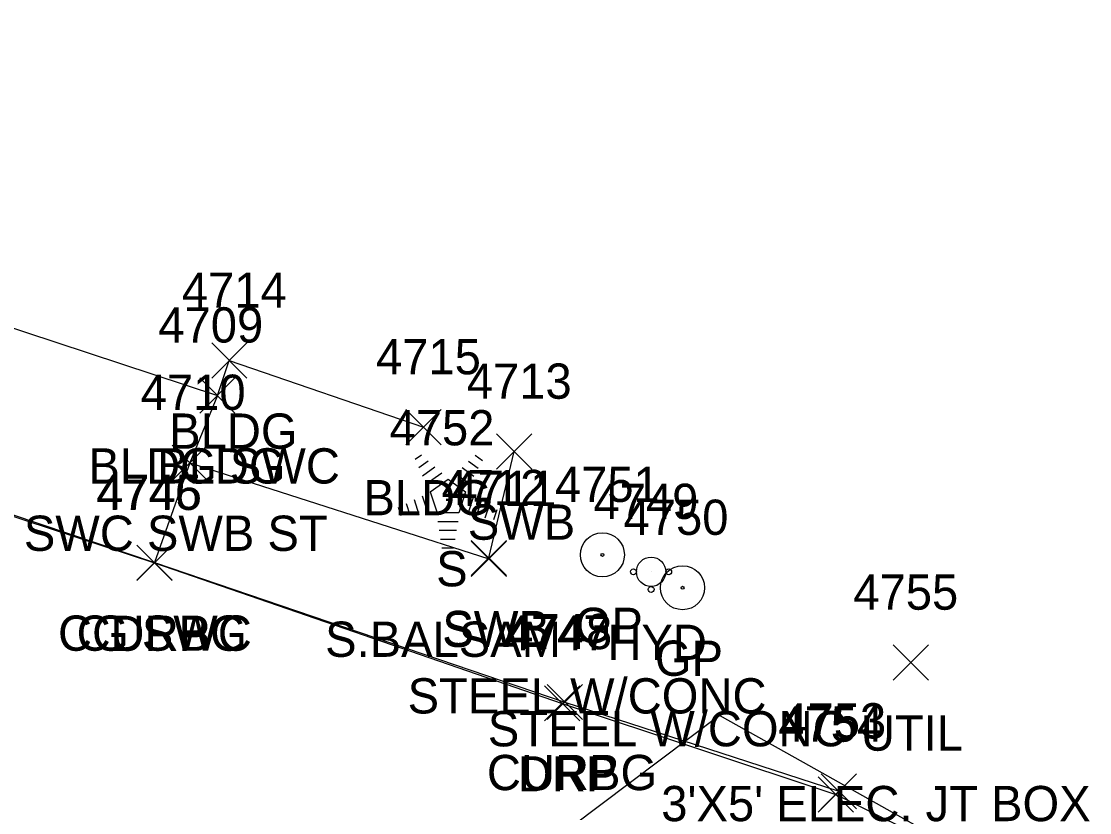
# Model space of a CAD drawing. Extents: x 49137 to 50946, y 9590 to 10709.
# Drawn here: x 50314.2 to 50374.8, y 10186.5 to 10231.4 of the extents above; entities that cross this region are included whole.
import ezdxf

# ---------------------------------------------------------------- set-up
doc = ezdxf.new("R2010")
doc.units = 0
for name, color, linetype in [('L_A', 7, 'Continuous'), ('L_C', 7, 'Continuous'), ('L_I', 7, 'Continuous'), ('L_TIC', 7, 'Continuous'), ('LBC', 7, 'Continuous'), ('LSOGP', 7, 'Continuous'), ('LTC', 7, 'Continuous'), ('PET', 7, 'Continuous'), ('R_A', 7, 'Continuous'), ('R_C', 7, 'Continuous'), ('R_I', 7, 'Continuous'), ('R_TIC', 7, 'Continuous'), ('RC', 7, 'Continuous'), ('RDP', 7, 'Continuous'), ('RGP', 7, 'Continuous'), ('RSW', 7, 'Continuous'), ('U_A', 7, 'Continuous'), ('U_C', 7, 'Continuous'), ('U_I', 7, 'Continuous'), ('UDEFAULT', 7, 'Continuous'), ('UWFH', 7, 'Continuous')]:
    doc.layers.add(name, color=color, linetype=linetype)

msp = doc.modelspace()

# ---------------------------------------------------------------- linework, layer by layer
at = {"layer": 'L_TIC'}
for points in [[(50325.045, 10211.173), (50327.045, 10213.173)], [(50327.045, 10211.173), (50325.045, 10213.173)], [(50324.367, 10209.198), (50326.367, 10211.198)], [(50326.367, 10209.198), (50324.367, 10211.198)], [(50336.06, 10207.397), (50338.06, 10209.397)], [(50338.06, 10207.397), (50336.06, 10209.397)]]:
    msp.add_lwpolyline(points, dxfattribs=at)
at = {"layer": 'LBC'}
msp.add_lwpolyline([(50282.222, 10227.148), (50292.804, 10223.645), (50292.299, 10221.382), (50307.138, 10216.211), (50325.367, 10210.198), (50326.045, 10212.173), (50337.06, 10208.397)], dxfattribs=at)
at = {"layer": 'LSOGP'}
msp.add_lwpolyline([(50368.109, 10184.028), (50363.359, 10186.695), (50358.609, 10189.361), (50353.858, 10192.028), (50331.98, 10175.564)], dxfattribs=at)
at = {"layer": 'LTC'}
for p, q in [((50336.59, 10206.572), (50336.944, 10206.83)), ((50339.988, 10206.813), (50340.407, 10206.508)), ((50336.799, 10206.107), (50337.329, 10206.491)), ((50339.617, 10206.464), (50340.166, 10206.065)), ((50337.009, 10205.641), (50337.713, 10206.152)), ((50337.219, 10205.175), (50338.097, 10205.813)), ((50338.875, 10205.768), (50339.684, 10205.179)), ((50339.246, 10206.116), (50339.925, 10205.622)), ((50337.443, 10204.72), (50338.455, 10205.455)), ((50338.455, 10205.455), (50339.452, 10204.73)), ((50336.989, 10204.501), (50337.319, 10203.482)), ((50337.443, 10204.72), (50337.83, 10203.527)), ((50339.452, 10204.73), (50339.061, 10203.527)), ((50339.889, 10204.459), (50339.551, 10203.419)), ((50335.622, 10203.851), (50335.774, 10203.383)), ((50336.078, 10204.068), (50336.289, 10203.416)), ((50336.533, 10204.285), (50336.804, 10203.449)), ((50340.334, 10204.208), (50340.046, 10203.324)), ((50340.779, 10203.958), (50340.541, 10203.229)), ((50339.061, 10203.527), (50337.83, 10203.527)), ((50341.223, 10203.708), (50341.036, 10203.134)), ((50339.022, 10203.027), (50337.878, 10203.027)), ((50338.939, 10202.527), (50337.95, 10202.527)), ((50338.855, 10202.027), (50338.023, 10202.027)), ((50338.771, 10201.527), (50338.096, 10201.527))]:
    msp.add_line(p, q, dxfattribs=at)
at = {"layer": 'PET'}
msp.add_lwpolyline([(50372.857, 10181.363), (50360.448, 10187.548)], dxfattribs=at)
at = {"layer": 'R_TIC'}
for points in [[(50324.367, 10209.198), (50326.367, 10211.198)], [(50326.367, 10209.198), (50324.367, 10211.198)], [(50341.21, 10206.009), (50343.21, 10208.009)], [(50343.21, 10206.009), (50341.21, 10208.009)], [(50322.8, 10205.377), (50324.8, 10207.377)], [(50324.8, 10205.377), (50322.8, 10207.377)], [(50322.8, 10205.377), (50324.8, 10207.377)], [(50324.8, 10205.377), (50322.8, 10207.377)], [(50339.772, 10199.922), (50341.772, 10201.922)], [(50341.772, 10199.922), (50339.772, 10201.922)], [(50339.773, 10199.974), (50341.773, 10201.974)], [(50341.773, 10199.974), (50339.773, 10201.974)], [(50320.801, 10199.709), (50322.801, 10201.709)], [(50322.801, 10199.709), (50320.801, 10201.709)], [(50320.801, 10199.709), (50322.801, 10201.709)], [(50322.801, 10199.709), (50320.801, 10201.709)], [(50320.808, 10199.695), (50322.808, 10201.695)], [(50322.808, 10199.695), (50320.808, 10201.695)], [(50343.924, 10191.725), (50345.924, 10193.725)], [(50345.924, 10191.725), (50343.924, 10193.725)], [(50344.075, 10191.8), (50346.075, 10193.8)], [(50346.075, 10191.8), (50344.075, 10193.8)], [(50359.619, 10186.733), (50361.619, 10188.733)], [(50361.619, 10186.733), (50359.619, 10188.733)], [(50359.448, 10186.548), (50361.448, 10188.548)], [(50361.448, 10186.548), (50359.448, 10188.548)]]:
    msp.add_lwpolyline(points, dxfattribs=at)
at = {"layer": 'RC'}
msp.add_lwpolyline([(50213.654, 10225.904), (50220.249, 10223.834), (50231.833, 10219.655), (50236.743, 10213.812), (50243.914, 10207.505), (50252.666, 10202.07), (50260.687, 10198.566), (50269.76, 10196.546), (50280.492, 10196.409), (50293.039, 10199.007), (50298.884, 10202.08), (50305.572, 10206.176), (50321.801, 10200.709), (50345.075, 10192.8), (50360.619, 10187.733)], dxfattribs=at)
at = {"layer": 'RDP'}
msp.add_lwpolyline([(50134.83, 10210.942), (50148.536, 10215.595), (50176.206, 10224.924), (50201.304, 10227.996), (50208.374, 10226.897), (50213.654, 10225.904), (50219.821, 10223.696), (50231.682, 10219.359), (50236.549, 10213.575), (50243.86, 10207.404), (50252.599, 10201.954), (50260.608, 10198.444), (50269.683, 10196.366), (50280.238, 10196.188), (50293.192, 10198.807), (50298.995, 10201.845), (50305.519, 10206.054), (50321.808, 10200.695), (50344.924, 10192.725), (50360.448, 10187.548)], dxfattribs=at)
at = {"layer": 'RGP'}
for p, q in [((50347.209, 10201.15), (50347.209, 10201.15)), ((50351.757, 10199.285), (50351.757, 10199.285))]:
    msp.add_line(p, q, dxfattribs=at)
for centre, radius in [((50347.209, 10201.15), 1.25), ((50347.209, 10201.15), 0.0833), ((50351.757, 10199.285), 1.25), ((50351.757, 10199.285), 0.0833)]:
    msp.add_circle(centre, radius, dxfattribs=at)
at = {"layer": 'RSW'}
for points in [[(50222.609, 10231.424), (50230.622, 10228.863), (50235.632, 10227.106), (50239.092, 10220.897), (50245.297, 10214.444), (50252.909, 10209.253), (50266.071, 10203.728), (50274.242, 10202.421), (50282.238, 10202.843), (50289.993, 10204.607), (50298.203, 10208.835), (50304.232, 10213.801), (50307.138, 10216.211), (50325.367, 10210.198), (50323.8, 10206.377), (50321.801, 10200.709)], [(50323.8, 10206.377), (50340.772, 10200.922), (50340.773, 10200.974), (50342.21, 10207.009)]]:
    msp.add_lwpolyline(points, dxfattribs=at)
at = {"layer": 'UDEFAULT'}
for points in [[(50363.705, 10194.038), (50365.705, 10196.038)], [(50365.705, 10194.038), (50363.705, 10196.038)]]:
    msp.add_lwpolyline(points, dxfattribs=at)
at = {"layer": 'UWFH'}
msp.add_line((50349.972, 10200.189), (50349.972, 10200.189), dxfattribs=at)
for centre, radius in [((50349.972, 10200.189), 0.833), ((50348.972, 10200.189), 0.167), ((50350.972, 10200.189), 0.167), ((50349.972, 10199.189), 0.167)]:
    msp.add_circle(centre, radius, dxfattribs=at)

# ---------------------------------------------------------------- texts
at = {"layer": 'L_A'}
for s, p in [('BLDG', (50322.635, 10207.173)), ('BLDG', (50321.957, 10205.198)), ('BLDG', (50333.651, 10203.397)), ('S', (50337.781, 10199.364))]:
    msp.add_text(s, height=2, dxfattribs=at).set_placement(p)
at = {"layer": 'L_C'}
msp.add_text('S.BALSAM', height=2, dxfattribs=at).set_placement((50331.481, 10195.364))
at = {"layer": 'L_I'}
for s, p in [('4714', (50323.352, 10215.173)), ('4709', (50322.02, 10213.198)), ('4715', (50334.368, 10211.397)), ('4752', (50335.135, 10207.364))]:
    msp.add_text(s, height=2, dxfattribs=at).set_placement(p)
at = {"layer": 'LTC'}
msp.add_text('.', height=1.037, rotation=270, dxfattribs=at).set_placement((50338.337, 10204.468))
at = {"layer": 'R_A'}
for s, p in [('BLDG SWC', (50318.052, 10205.198)), ('SWB', (50339.573, 10202.009)), ('SWC SWB ST', (50314.391, 10201.377)), ('SWC SWB ST', (50314.391, 10201.377)), ('CG SWC', (50316.329, 10195.709)), ('CURBG', (50317.384, 10195.709)), ('DRP', (50319.296, 10195.695)), ('SWB', (50338.134, 10195.922)), ('SWB', (50338.135, 10195.974)), ('GP', (50345.642, 10196.15)), ('GP', (50350.19, 10194.285)), ('CURBG', (50340.658, 10187.8)), ('DRP', (50342.412, 10187.725))]:
    msp.add_text(s, height=2, dxfattribs=at).set_placement(p)
at = {"layer": 'R_C'}
for p in [(50336.162, 10192.15), (50340.71, 10190.285)]:
    msp.add_text('STEEL W/CONC', height=2, dxfattribs=at).set_placement(p)
at = {"layer": 'R_I'}
for s, p in [('4709', (50322.02, 10213.198)), ('4713', (50339.518, 10210.009)), ('4710', (50321.021, 10209.377)), ('4710', (50321.021, 10209.377)), ('4746', (50318.493, 10203.695)), ('4745', (50318.541, 10203.709)), ('4745', (50318.541, 10203.709)), ('4712', (50338.08, 10203.974)), ('4711', (50338.646, 10203.922)), ('4751', (50344.516, 10204.15)), ('4750', (50348.411, 10202.285)), ('4747', (50341.664, 10195.725)), ('4748', (50341.816, 10195.8)), ('4754', (50357.188, 10190.548)), ('4753', (50357.359, 10190.733))]:
    msp.add_text(s, height=2, dxfattribs=at).set_placement(p)
at = {"layer": 'U_A'}
for s, p in [('HYD', (50347.492, 10195.189)), ('UTIL', (50361.87, 10190.038))]:
    msp.add_text(s, height=2, dxfattribs=at).set_placement(p)
at = {"layer": 'U_C'}
msp.add_text("3'X5' ELEC. JT BOX", height=2, dxfattribs=at).set_placement((50350.548, 10186.038))
at = {"layer": 'U_I'}
for s, p in [('4749', (50346.705, 10203.189)), ('4755', (50361.445, 10198.038))]:
    msp.add_text(s, height=2, dxfattribs=at).set_placement(p)

doc.saveas('drawing.dxf')
